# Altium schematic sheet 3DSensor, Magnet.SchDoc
size Letter; Organization: Cegep Limoilou; Address1: 1300, 8e Avenue; Address2: Québec, QC; Address3: Canada; Address4: G1J 5L5; Revision: Enseignants; SheetNumber: 4; SheetTotal: 8; Conception: Ilyes Gharmoul; Titre: 3D sensor and Magnet sensor; Modification: Ilyes G
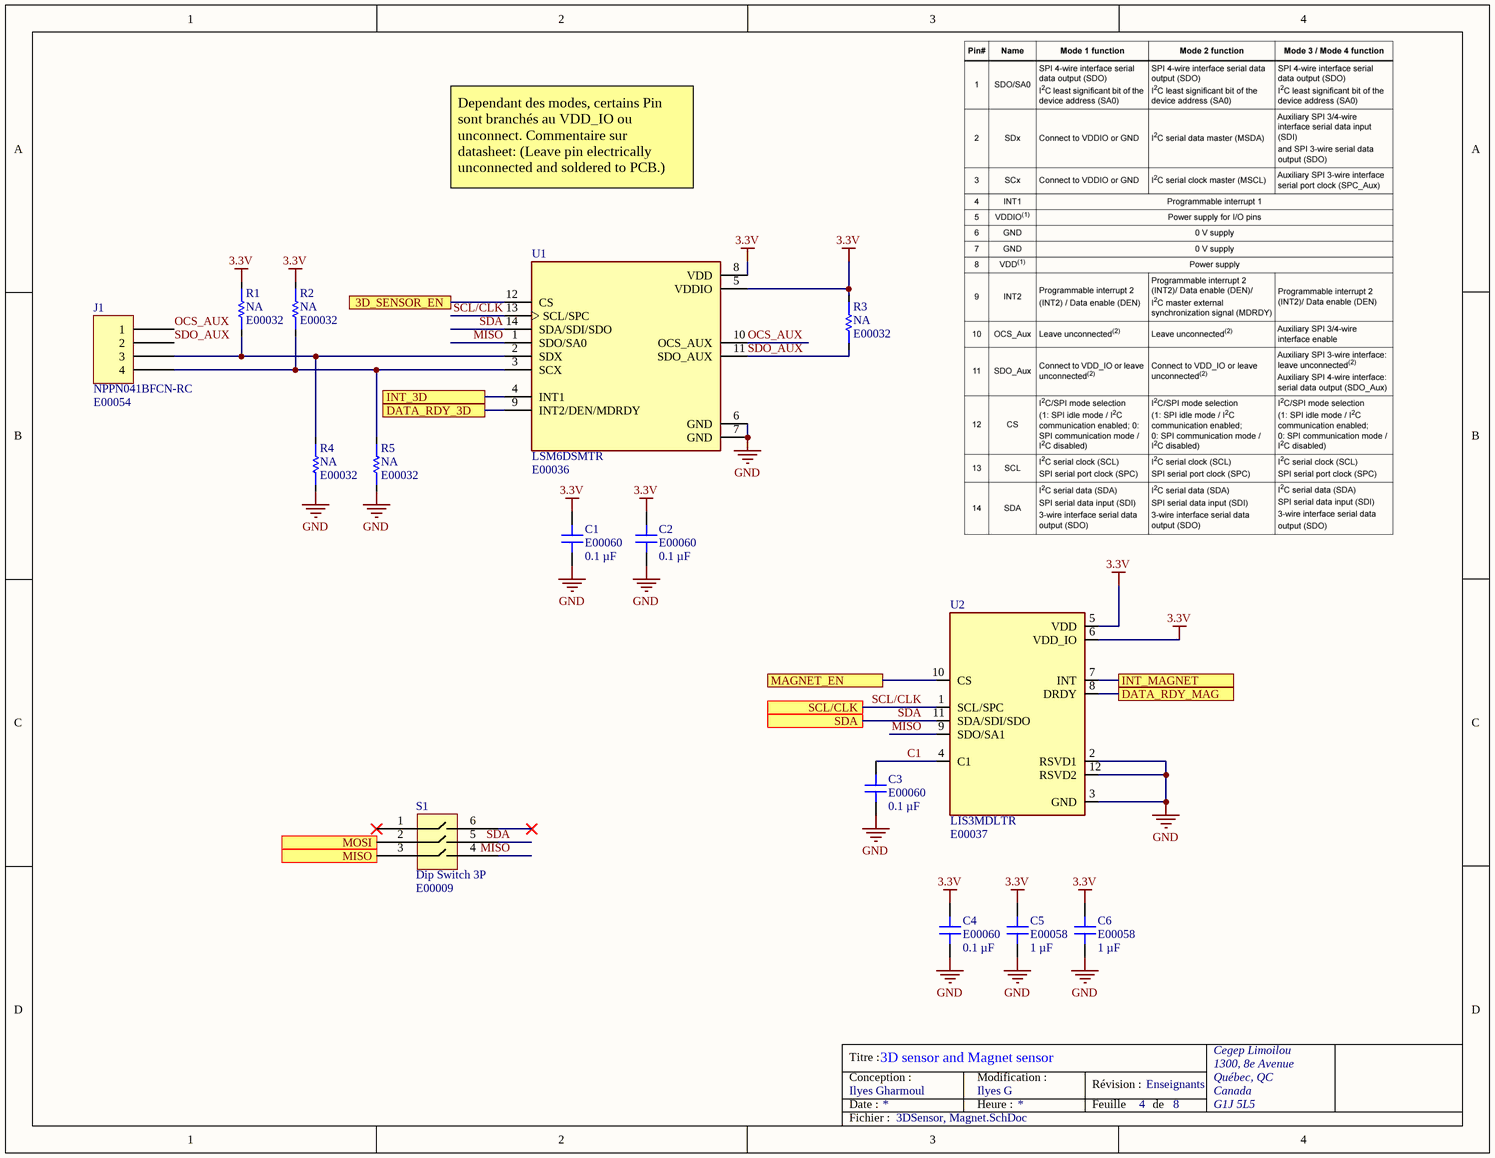
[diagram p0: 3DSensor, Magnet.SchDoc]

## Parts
C1  ADAM Inventory Number 1: E00060  [CAP 0603]  (hidden comment: 0.1 µF)
C2  ADAM Inventory Number 1: E00060  [CAP 0603]  (hidden comment: 0.1 µF)
C3  ADAM Inventory Number 1: E00060  [CAP 0603]  (hidden comment: 0.1 µF)
C4  ADAM Inventory Number 1: E00060  [CAP 0603]  (hidden comment: 0.1 µF)
C5  ADAM Inventory Number 1: E00058  [CAP 0603]  (hidden comment: 1 µF)
C6  ADAM Inventory Number 1: E00058  [CAP 0603]  (hidden comment: 1 µF)
J1  NPPN041BFCN-RC  ADAM Inventory Number 1: E00054  [CONN FEM HEADER 4PIN]
R1  NA  ADAM Inventory Number 1: E00032  [RES 0603]
R2  NA  ADAM Inventory Number 1: E00032  [RES 0603]
R3  NA  ADAM Inventory Number 1: E00032  [RES 0603]
R4  NA  ADAM Inventory Number 1: E00032  [RES 0603]
R5  NA  ADAM Inventory Number 1: E00032  [RES 0603]
S1  Dip Switch 3P  ADAM Inventory Number 1: E00009  [DIPSWITCH SMD 3P]
U1  LSM6DSMTR  ADAM Inventory Number 1: E00036  [PQFN50P300X250X86-14N]
U2  LIS3MDLTR  ADAM Inventory Number 1: E00037  [XDCR_LIS3MDLTR]

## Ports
3D_SENSOR_EN, DATA_RDY_3D, DATA_RDY_MAG, INT_3D, INT_MAGNET, MAGNET_EN, MISO, MOSI, SCL/CLK, SDA

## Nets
3.3V: C1.2 C2.2 C4.2 C5.2 C6.2 R1.2 R2.2 R3.2 U1.5(VDDIO) U1.8(VDD) U2.5(VDD) U2.6(VDD_IO)
GND: C1.1 C2.1 C3.1 C4.1 C5.1 C6.1 R4.1 R5.1 U1.6(GND) U1.7(GND) U2.2(RSVD1) U2.3(GND) U2.12(RSVD2)
3D_SENSOR_EN: U1.12(CS) ; port 3D_SENSOR_EN
C1: C3.2 U2.4(C1)
DATA_RDY_3D: U1.9(INT2/DEN/MDRDY) ; port DATA_RDY_3D
DATA_RDY_MAG: U2.8(DRDY) ; port DATA_RDY_MAG
INT_3D: U1.4(INT1) ; port INT_3D
INT_MAGNET: U2.7(INT) ; port INT_MAGNET
MAGNET_EN: U2.10(CS) ; port MAGNET_EN
MISO: S1.4 U1.1(SDO/SA0) U2.9(SDO/SA1)
MISO: S1.3 ; port MISO  [a separate net that carries the same name]
MOSI: S1.2 ; port MOSI
OCS_AUX: J1.1 U1.10(OCS_AUX)
SCL/CLK: U1.13(SCL/SPC) U2.1(SCL/SPC) ; port SCL/CLK
SDA: S1.5 U1.14(SDA/SDI/SDO) U2.11(SDA/SDI/SDO) ; port SDA
SDO_AUX: J1.2 R3.1 U1.11(SDO_AUX)
NetJ1_3: J1.3 R1.1 R4.2 U1.2(SDX)
NetJ1_4: J1.4 R2.1 R5.2 U1.3(SCX)

Not connected (* = marked no-connect by the designer): S1 1* 6*

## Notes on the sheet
- Dependant des modes, certains Pin sont branchés au VDD_IO ou unconnect. Commentaire sur datasheet: (Leave pin electrically unconnected and soldered to PCB.)

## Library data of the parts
C1-C4 = CAP CER 0.1UF 50V X7R 0603: Manufacturer Part Number 1: C0603C104K5RAC7411; manufacturer: KEMET; Tolerance: ±10%
C5 C6 = CAP CER 1UF 16V X7R 0603: Manufacturer Part Number 1: C0603C105K4RACAUTO; manufacturer: KEMET; Tolerance: ±10%
J1 = CONN FEM HEADER 4POS: CONN HDR 4POS 0.079 GOLD; Manufacturer: Sullins Connector Solutions; Connector Type: Header; Contact Length - Post: 0.094" (2.40mm); Current Rating (Amps): 2A; Material Flammability Rating: UL94 V-0; Number of Positions: 4; Number of Positions Loaded: All; Pitch - Mating: 0.079" (2.00mm); Style: Board to Board
R1-R5 = NA Res 0603: No resistance, just in case; Manufacturer Part Number 1: RC0603JR-070RL
S1 = Dip Switch 3P: Dip Switch SPST 3 Position Surface Mount Slide (Standard) Actuator 25mA 24VDC; Manufacturer Part Number 1: DS04-254-2-03BK-SMT; Manufacturer: CUI
U1 = LSM6DSMTR: Accelerometer, Gyroscope, Temperature, 6 Axis Sensor I²C, SPI Output
U2 = LIS3MDLTR: Magnetoresistive Sensor X, Y, Z Axis 12-LGA (2x2)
